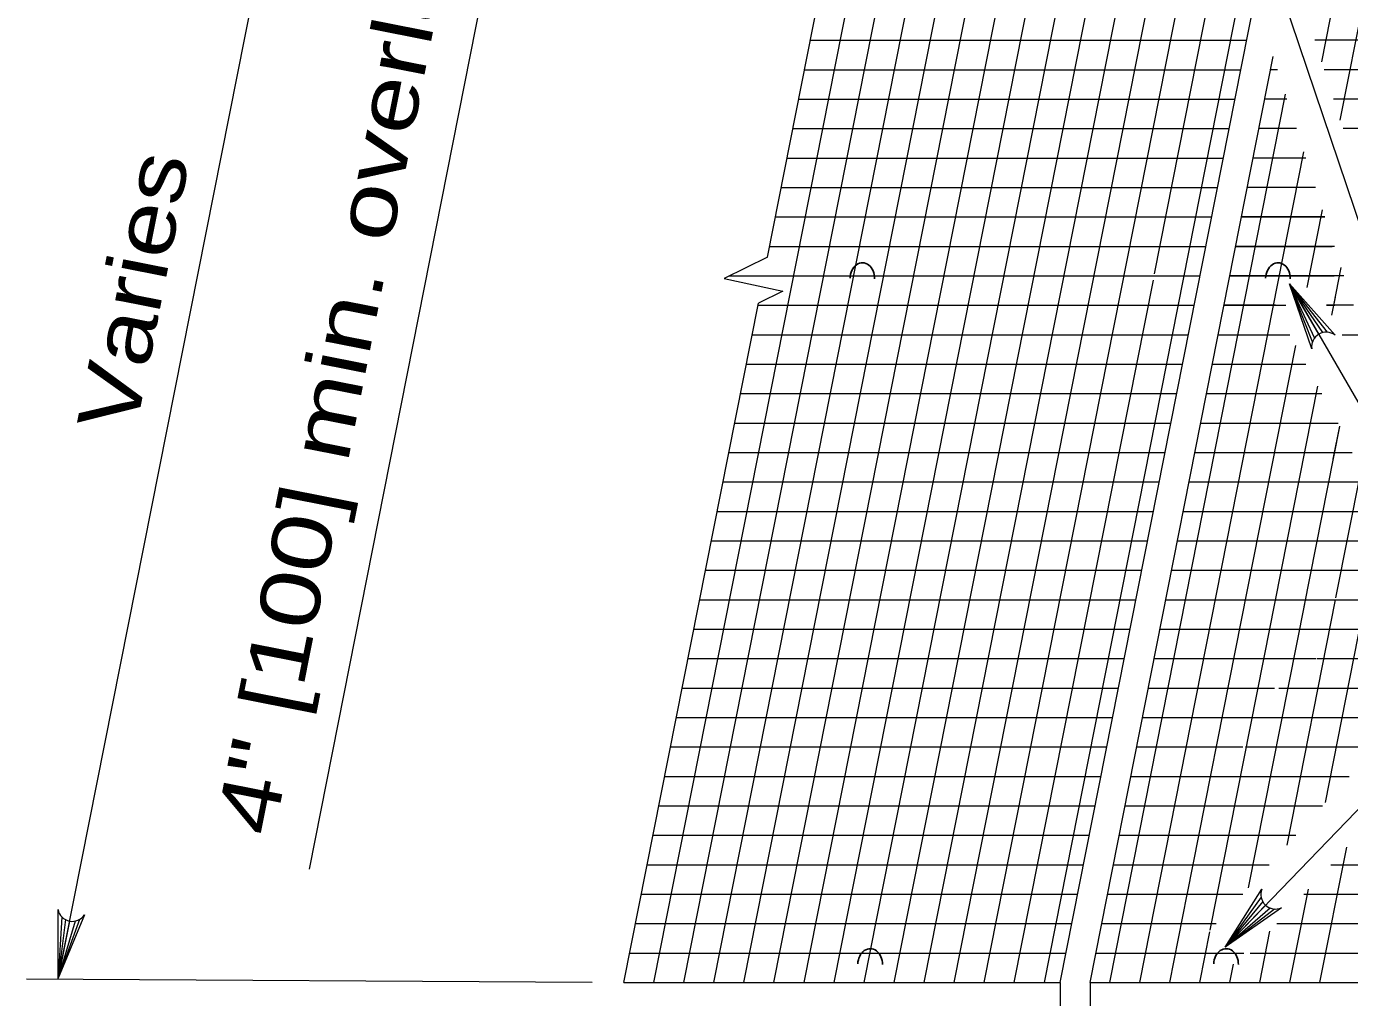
# Model space of a CAD drawing. Extents: x 1083.1 to 1117.1, y 719.4 to 741.4.
# Drawn here: x 1097.576 to 1101.052, y 727.359 to 729.91 of the extents above; entities that cross this region are included whole.
import ezdxf

# ---------------------------------------------------------------- set-up
doc = ezdxf.new("R2010")
doc.units = 0
doc.header["$LTSCALE"] = 0.062
doc.layers.add('1', color=7, linetype='Continuous', lineweight=13)

msp = doc.modelspace()

# ---------------------------------------------------------------- linework, layer by layer
at = {"layer": '1'}
for p, q in [((1097.65958, 727.40708), (1098.36458, 730.96625)), ((1099.22433, 727.39792), (1099.92858, 730.95708)), ((1099.30317, 727.39792), (1100.00742, 730.95708)), ((1099.38208, 727.39792), (1100.08633, 730.95708)), ((1099.461, 727.39792), (1100.16525, 730.95708)), ((1099.52283, 729.30358), (1099.84967, 730.95708)), ((1099.53983, 727.39792), (1100.24408, 730.95708)), ((1099.61875, 727.39792), (1100.323, 730.95708)), ((1099.69758, 727.39792), (1100.40183, 730.95708)), ((1099.7765, 727.39792), (1100.48075, 730.95708)), ((1099.85533, 727.39792), (1100.55958, 730.95708)), ((1100.97892, 729.817), (1101.20433, 730.95708)), ((1101.46192, 728.25383), (1100.61817, 730.75558)), ((1098.91858, 730.73125), (1098.3185, 727.69617)), ((1099.93425, 727.39792), (1100.5815, 730.66925)), ((1100.01308, 727.39792), (1100.63042, 730.5175)), ((1100.092, 727.39792), (1100.67925, 730.36583)), ((1100.53975, 729.26017), (1100.72825, 730.21375)), ((1101.02758, 729.66417), (1101.11492, 730.10608)), ((1100.25067, 727.39792), (1100.77708, 730.06192)), ((1100.29158, 727.39792), (1100.80258, 729.98292)), ((1099.63575, 729.87383), (1100.78125, 729.87383)), ((1101.19833, 729.87383), (1100.96083, 729.87383)), ((1100.37042, 727.39792), (1100.8515, 729.83117)), ((1099.62042, 729.7965), (1100.76592, 729.7965)), ((1100.86258, 729.7965), (1100.84425, 729.7965)), ((1101.18775, 729.7965), (1100.9855, 729.7965)), ((1100.42192, 727.39792), (1100.88333, 729.73225)), ((1099.60508, 729.71908), (1100.75058, 729.71908)), ((1100.8875, 729.71908), (1100.82892, 729.71908)), ((1101.17717, 729.71908), (1101.01008, 729.71908)), ((1099.58975, 729.64175), (1100.73525, 729.64175)), ((1100.91242, 729.64175), (1100.81358, 729.64175)), ((1101.16875, 729.64175), (1101.03475, 729.64175)), ((1099.57442, 729.56442), (1100.71992, 729.56442)), ((1100.50083, 727.39792), (1100.93217, 729.58042)), ((1100.93742, 729.56442), (1100.79825, 729.56442)), ((1099.55908, 729.487), (1100.70467, 729.487)), ((1100.96233, 729.487), (1100.78292, 729.487)), ((1100.94067, 729.2245), (1100.98108, 729.42875)), ((1099.54383, 729.40967), (1100.68942, 729.40967)), ((1100.98725, 729.40967), (1100.76758, 729.40967)), ((1100.76808, 729.40967), (1100.98725, 729.40967)), ((1099.5285, 729.33225), (1100.67408, 729.33225)), ((1101.01217, 729.33225), (1100.75225, 729.33225)), ((1100.75283, 729.33225), (1101.00608, 729.33225)), ((1099.52283, 729.30358), (1099.40892, 729.24833)), ((1101.01033, 729.17817), (1101.02992, 729.27717)), ((1099.4225, 729.25492), (1100.65825, 729.25492)), ((1100.17092, 727.39792), (1100.5365, 729.24375)), ((1100.7375, 729.25492), (1101.011, 729.25492)), ((1100.97117, 729.10167), (1100.89425, 729.23417)), ((1100.96008, 729.092), (1100.89425, 729.23417)), ((1100.95417, 729.0815), (1100.89425, 729.23417)), ((1100.98175, 729.10592), (1100.89425, 729.23417)), ((1100.99408, 729.10683), (1100.89425, 729.23417)), ((1099.14542, 727.39792), (1099.49908, 729.18333)), ((1099.49792, 729.1775), (1100.6435, 729.1775)), ((1100.85258, 729.1775), (1100.72158, 729.1775)), ((1100.72225, 729.1775), (1100.85258, 729.1775)), ((1100.8575, 729.1775), (1100.85258, 729.1775)), ((1100.85258, 729.1775), (1100.88417, 729.1775)), ((1100.92992, 729.17025), (1100.93058, 729.17367)), ((1101.062, 729.1775), (1100.99092, 729.1775)), ((1100.99092, 729.1775), (1101.01342, 729.1775)), ((1101.00508, 729.15125), (1101.01458, 729.19908)), ((1101.01458, 729.19908), (1101.01458, 729.19917)), ((1099.48258, 729.10017), (1100.62817, 729.10017)), ((1100.707, 729.10017), (1100.89475, 729.10017)), ((1101.03267, 729.10017), (1101.08692, 729.10017)), ((1100.62517, 727.62842), (1100.91042, 729.0715)), ((1099.46733, 729.02275), (1100.61283, 729.02275)), ((1100.69167, 729.02275), (1100.937, 729.02275)), ((1100.84042, 728.31825), (1100.96833, 728.96533)), ((1099.452, 728.94542), (1100.5975, 728.94542)), ((1100.67642, 728.94542), (1100.97925, 728.94542)), ((1099.43667, 728.868), (1100.58217, 728.868)), ((1100.66108, 728.868), (1101.0215, 728.868)), ((1100.9325, 728.38542), (1101.02617, 728.85933)), ((1101.00883, 728.7735), (1101.02592, 728.85983)), ((1099.42133, 728.79067), (1100.56683, 728.79067)), ((1100.64575, 728.79067), (1101.05875, 728.79067)), ((1101.016, 728.4085), (1101.08125, 728.73875)), ((1099.406, 728.71325), (1100.5515, 728.71325)), ((1100.6305, 728.71325), (1101.10592, 728.71325)), ((1099.39067, 728.63592), (1100.53617, 728.63592)), ((1100.61517, 728.63592), (1101.14817, 728.63592)), ((1099.37533, 728.5585), (1100.52092, 728.5585)), ((1100.59983, 728.5585), (1101.1565, 728.5585)), ((1099.36, 728.48117), (1100.50558, 728.48117)), ((1100.58458, 728.48117), (1101.20433, 728.48117)), ((1100.98858, 727.87075), (1101.09675, 728.41808)), ((1099.34467, 728.40383), (1100.49025, 728.40383)), ((1100.56925, 728.40383), (1101.23992, 728.40383)), ((1100.78658, 727.64708), (1100.93408, 728.39325)), ((1100.88758, 727.759), (1101.015, 728.40358)), ((1100.68575, 727.53542), (1100.84442, 728.33617)), ((1099.32933, 728.32642), (1100.47492, 728.32642)), ((1100.554, 728.32642), (1101.2815, 728.32642)), ((1099.314, 728.24908), (1100.45958, 728.24908)), ((1100.53875, 728.24908), (1100.964, 728.24908)), ((1100.96708, 728.24908), (1101.32, 728.24908)), ((1099.29875, 728.17167), (1100.44425, 728.17167)), ((1100.52342, 728.17167), (1100.85442, 728.17167)), ((1100.86633, 728.17167), (1101.26033, 728.17167)), ((1099.28342, 728.09433), (1100.42892, 728.09433)), ((1100.50817, 728.09433), (1100.82042, 728.09433)), ((1100.82008, 728.09433), (1101.19042, 728.09433)), ((1099.26808, 728.01692), (1100.41358, 728.01692)), ((1100.49283, 728.01692), (1100.77125, 728.01692)), ((1100.77883, 728.01692), (1101.12058, 728.01692)), ((1099.25275, 727.93958), (1100.39825, 727.93958)), ((1100.4775, 727.93958), (1100.775, 727.93958)), ((1100.77542, 727.93958), (1101.05067, 727.93958)), ((1099.23742, 727.86217), (1100.38292, 727.86217)), ((1100.46225, 727.86217), (1100.78642, 727.86217)), ((1100.76775, 727.86217), (1100.98083, 727.86217)), ((1099.22208, 727.78483), (1100.36758, 727.78483)), ((1100.44692, 727.78483), (1100.7675, 727.78483)), ((1100.76575, 727.78483), (1100.911, 727.78483)), ((1100.974, 727.39792), (1101.04433, 727.75358)), ((1099.20675, 727.70742), (1100.35233, 727.70742)), ((1100.43167, 727.70742), (1100.77125, 727.70742)), ((1100.76408, 727.70742), (1100.84108, 727.70742)), ((1101.00225, 727.70742), (1103.00717, 727.70742)), ((1100.89508, 727.39792), (1100.94358, 727.64308)), ((1099.19142, 727.63008), (1100.337, 727.63008)), ((1100.41633, 727.63008), (1100.77125, 727.63008)), ((1100.57958, 727.39792), (1100.62533, 727.62908)), ((1100.81958, 727.62225), (1100.72508, 727.49092)), ((1100.82383, 727.61067), (1100.72508, 727.49092)), ((1100.93167, 727.63008), (1102.99192, 727.63008)), ((1097.66875, 727.57067), (1097.65967, 727.40917)), ((1100.83083, 727.60167), (1100.72508, 727.49092)), ((1100.84325, 727.59375), (1100.72508, 727.49092)), ((1100.855, 727.591), (1100.72508, 727.49092)), ((1097.71542, 727.56342), (1097.65967, 727.40917)), ((1097.67858, 727.56325), (1097.65967, 727.40917)), ((1097.68933, 727.55942), (1097.65967, 727.40917)), ((1097.704, 727.55942), (1097.65967, 727.40917)), ((1099.17608, 727.55267), (1100.32167, 727.55267)), ((1100.401, 727.55267), (1100.70133, 727.55267)), ((1100.86117, 727.55267), (1102.97658, 727.55267)), ((1100.6585, 727.39792), (1100.68492, 727.53117)), ((1100.81625, 727.39792), (1100.84283, 727.53258)), ((1099.16075, 727.47533), (1100.30633, 727.47533)), ((1100.38575, 727.47533), (1100.774, 727.47533)), ((1100.79067, 727.47533), (1102.96133, 727.47533)), ((1100.73733, 727.39792), (1100.74692, 727.44642)), ((1099.06217, 727.39792), (1097.57625, 727.40708)), ((1099.14542, 727.39792), (1100.29158, 727.39792)), ((1100.29158, 727.39792), (1100.29158, 726.26333)), ((1100.37042, 727.39792), (1100.37042, 726.26333)), ((1100.37042, 727.39792), (1102.946, 727.39792))]:
    msp.add_line(p, q, dxfattribs=at)
for points in [[(1099.40892, 729.24833), (1099.5635, 729.21458), (1099.49908, 729.18333)], [(1101.03708, 729.25492), (1100.94925, 729.25492), (1100.73692, 729.25492)], [(1100.89425, 729.23417), (1101.46192, 728.25383), (1100.72508, 727.49092)], [(1100.9525, 729.06333), (1100.89425, 729.23417), (1101.01375, 729.09883)], [(1100.87292, 727.59442), (1100.72508, 727.49092), (1100.82175, 727.64333)], [(1097.72867, 727.57592), (1097.65967, 727.40917), (1097.65925, 727.58967)]]:
    msp.add_lwpolyline(points, dxfattribs=at)
for centre, start, end in [((1100.9903, 729.06874), 52.22308, 188.04921), ((1100.85718, 727.62926), 158.38986, 294.21599), ((1097.69669, 727.59682), 190.91743, 326.74356)]:
    msp.add_arc(centre, 0.0382, start, end, dxfattribs=at)
at = {"layer": '1', "lineweight": 25}
for centre in [(1099.77196, 729.24819), (1100.8637, 729.24819), (1099.79245, 727.4459), (1100.72743, 727.4459)]:
    msp.add_ellipse(centre, major_axis=(0.00099, 0.04097), ratio=0.78812, start_param=4.7123995, end_param=7.8539922, dxfattribs=at)

# ---------------------------------------------------------------- texts
at = {"layer": '1'}
for s, width, p in [('4" [100] min. overlap', 1.3, (1098.2255, 727.77817)), ('Varies', 1.25, (1097.86167, 728.8375))]:
    msp.add_text(s, height=0.156, rotation=78.819, dxfattribs=dict(at, width=width)).set_placement(p)

doc.saveas('drawing.dxf')
